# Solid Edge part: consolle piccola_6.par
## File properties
Last saved by: i.fialdini
Revision: 62
Tipo di contenuto documento: 0
Accuracy: 0.990
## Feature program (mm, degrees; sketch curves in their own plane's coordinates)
body "unnamed Body 1"
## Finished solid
Body 1: solid body, 60 faces, 206 edges, 206 vertices, 13 internal voids.
  Faces by surface: cylinder 60
  Edges by curve: curve on surface 128, spline 78
Bounding box of the edges (mm): 418.931 x 383.483 x 16.000, from (-209.4899, -907.8984, 325.0793) to (209.4407, -524.4153, 341.0793).
Cylindrical faces by radius (mm): R3 x13, R4 x13, R6.5 x2, R8 x28, R10.5 x4
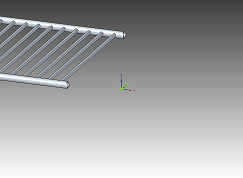
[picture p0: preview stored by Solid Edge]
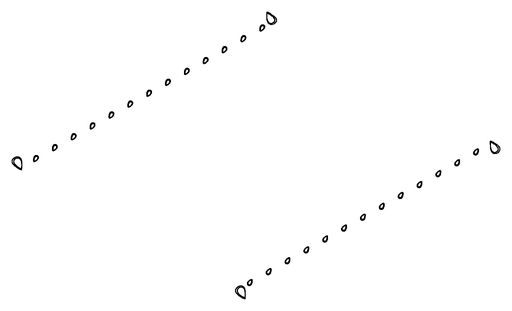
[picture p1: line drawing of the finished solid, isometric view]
